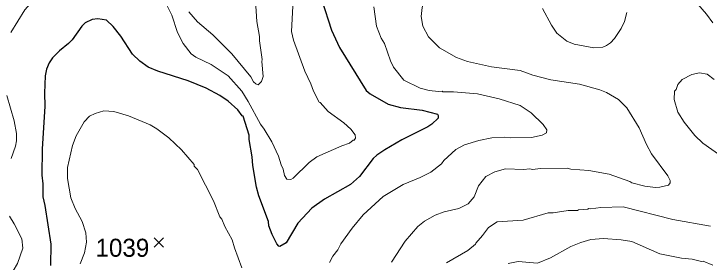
# Model space of a CAD drawing. Extents: x 265.7 to 292.1, y 7676.2 to 7704.2.
# Drawn here: x 287.156 to 290.234, y 7683.775 to 7684.876 of the extents above; entities that cross this region are included whole.
import ezdxf
from ezdxf.enums import TextEntityAlignment as Align

# ---------------------------------------------------------------- set-up
doc = ezdxf.new("R2010")
doc.units = 0
doc.header["$LTSCALE"] = 0.032
for name, color, linetype, lineweight in [('1', 7, 'Continuous', 25), ('2', 7, 'Continuous', 13), ('21', 7, 'Continuous', 25)]:
    doc.layers.add(name, color=color, linetype=linetype, lineweight=lineweight)
doc.layers.add('61', color=7, linetype='Continuous')

msp = doc.modelspace()

# ---------------------------------------------------------------- linework, layer by layer
at = {"layer": '1'}
for points in [[(288.519, 7684.9379), (288.5621, 7684.8038), (288.598, 7684.7272), (288.7161, 7684.5357), (288.7329, 7684.5214), (288.8127, 7684.4759), (288.8685, 7684.4607), (288.9643, 7684.4487), (289.0313, 7684.4312), (289.0353, 7684.4256), (289.0345, 7684.4128), (289.0066, 7684.3873), (288.9882, 7684.3753), (288.8733, 7684.3171), (288.7983, 7684.2732), (288.7632, 7684.2492), (288.7472, 7684.2341), (288.6866, 7684.1543), (288.6467, 7684.12), (288.5318, 7684.0545), (288.4751, 7684.0147), (288.4129, 7683.9484), (288.3618, 7683.8615), (288.3339, 7683.8447), (288.3283, 7683.8455), (288.3195, 7683.8559), (288.2988, 7683.8974), (288.2844, 7683.9357), (288.2828, 7683.9548), (288.2405, 7684.0697), (288.2302, 7684.108), (288.2142, 7684.2038), (288.211, 7684.2421), (288.1982, 7684.3187), (288.1982, 7684.3378), (288.1711, 7684.4216), (288.1671, 7684.4232), (288.1472, 7684.4511), (288.1049, 7684.4894), (288.0674, 7684.5142), (288.0067, 7684.5461), (287.9269, 7684.5796), (287.7929, 7684.6211), (287.7498, 7684.6395), (287.7131, 7684.6658)], [(287.5024, 7684.8509), (287.4721, 7684.8358), (287.4561, 7684.8206), (287.4138, 7684.7608), (287.3979, 7684.744), (287.3572, 7684.7121), (287.3269, 7684.6802), (287.3125, 7684.6586), (287.2997, 7684.6307), (287.2949, 7684.6012), (287.291, 7684.5246), (287.2934, 7684.4671), (287.2814, 7684.2756), (287.2798, 7684.1607), (287.2838, 7684.1224), (287.2838, 7684.0649), (287.2926, 7684.0266), (287.3197, 7683.8543), (287.3181, 7683.7601)], [(287.7131, 7684.6658), (287.6812, 7684.6977), (287.6293, 7684.7767), (287.595, 7684.8198), (287.5655, 7684.8477), (287.528, 7684.8533), (287.5024, 7684.8509)]]:
    msp.add_lwpolyline(points, dxfattribs=at)
at = {"layer": '2'}
for points in [[(287.5567, 7685.2331), (287.4936, 7685.2004), (287.4466, 7685.1621), (287.4107, 7685.123), (287.3325, 7685.0241), (287.2622, 7684.9602), (287.2048, 7684.8932), (287.1417, 7684.7927)], [(289.0106, 7685.1119), (289.0162, 7685.072), (289.0106, 7685.0233), (288.9794, 7684.9507), (288.9643, 7684.9044), (288.9587, 7684.8645), (288.9667, 7684.8214)], [(290.2505, 7684.8353), (290.2227, 7684.8741), (290.1357, 7684.9762)], [(287.9301, 7684.8852), (287.9692, 7684.8406), (288.0363, 7684.7831), (288.1208, 7684.6985), (288.2046, 7684.5964), (288.2174, 7684.574), (288.227, 7684.5653), (288.2381, 7684.5613), (288.2525, 7684.5756), (288.2597, 7684.598), (288.2541, 7684.665), (288.2557, 7684.673), (288.2429, 7684.756), (288.2437, 7684.7751), (288.231, 7684.8422), (288.2254, 7684.9331)], [(288.3906, 7684.9092), (288.3858, 7684.7975), (288.3937, 7684.7592), (288.4448, 7684.6219), (288.4704, 7684.5661), (288.4823, 7684.5325), (288.5071, 7684.4839), (288.5118, 7684.4831), (288.5469, 7684.4432), (288.6164, 7684.3929), (288.6483, 7684.3642), (288.6674, 7684.3402), (288.6682, 7684.3243), (288.6627, 7684.3163), (288.6587, 7684.3163), (288.6419, 7684.3027), (288.6084, 7684.2908), (288.4967, 7684.2413), (288.464, 7684.2173), (288.393, 7684.1471), (288.3818, 7684.1415), (288.3642, 7684.1431), (288.3538, 7684.1591), (288.3475, 7684.1878), (288.3387, 7684.207), (288.3275, 7684.2453), (288.298, 7684.3091), (288.2645, 7684.365), (288.2477, 7684.3873), (288.1935, 7684.4879), (288.1647, 7684.5325), (288.1041, 7684.6012), (288.0291, 7684.6514), (287.9621, 7684.6834), (287.9405, 7684.6985), (287.9054, 7684.7448), (287.8807, 7684.7927), (287.8551, 7684.8693), (287.8352, 7684.9108)], [(289.3553, 7684.3259), (289.4479, 7684.3275), (289.4957, 7684.3378), (289.5141, 7684.349), (289.5157, 7684.3618), (289.4989, 7684.3857), (289.4471, 7684.4368), (289.3984, 7684.4695), (289.3042, 7684.4998), (289.2085, 7684.5206), (289.1031, 7684.5301), (289.0553, 7684.5301), (289.0529, 7684.5333), (289.0361, 7684.5317), (288.9946, 7684.5365), (288.9547, 7684.5461), (288.8829, 7684.582), (288.8374, 7684.6395), (288.823, 7684.6682), (288.7967, 7684.7448), (288.7824, 7684.7687), (288.7608, 7684.8214), (288.7496, 7684.9076)], [(289.87, 7684.882), (289.8596, 7684.8422), (289.8452, 7684.8102), (289.8157, 7684.7663), (289.7982, 7684.748), (289.7798, 7684.7352), (289.7639, 7684.7288), (289.724, 7684.7248), (289.6362, 7684.7408), (289.6043, 7684.7552), (289.5604, 7684.7903), (289.5364, 7684.8254), (289.4973, 7684.8996)], [(288.9667, 7684.8214), (288.9914, 7684.7735), (289.0401, 7684.7256), (289.1159, 7684.6818), (289.1638, 7684.6642), (289.2707, 7684.6411), (289.3984, 7684.6243), (289.4542, 7684.6036), (289.534, 7684.5828), (289.6609, 7684.5637), (289.7511, 7684.5397), (289.7798, 7684.5269), (289.8325, 7684.4958), (289.87, 7684.4591), (289.925, 7684.3706), (289.957, 7684.2963), (289.9793, 7684.2549), (290.0511, 7684.1575), (290.0623, 7684.1368), (290.0615, 7684.1272), (290.0551, 7684.1168), (290.016, 7684.1072), (289.9969, 7684.1064), (289.949, 7684.112), (289.8915, 7684.1264), (289.8827, 7684.132), (289.7918, 7684.1655), (289.7016, 7684.1814), (289.6218, 7684.187), (289.6059, 7684.1918), (289.4862, 7684.191), (289.4542, 7684.1862), (289.4383, 7684.1886), (289.4143, 7684.1862), (289.333, 7684.1886), (289.2851, 7684.1758), (289.2452, 7684.1543), (289.2133, 7684.1128), (289.1941, 7684.0649), (289.167, 7684.0338), (289.1255, 7684.0131), (289.0616, 7683.9979), (289.0217, 7683.9835), (288.9739, 7683.9572), (288.9443, 7683.9325), (288.8885, 7683.8686), (288.8286, 7683.7753)], [(290.3009, 7684.2357), (290.2067, 7684.3027), (290.1708, 7684.337), (290.1245, 7684.3953), (290.0958, 7684.44), (290.0798, 7684.4958), (290.0814, 7684.5325), (290.0878, 7684.5405), (290.0958, 7684.5629), (290.115, 7684.5852), (290.158, 7684.6075), (290.1916, 7684.6139), (290.2251, 7684.6083), (290.257, 7684.5852)], [(287.125, 7684.5134), (287.1577, 7684.4017), (287.1681, 7684.3458), (287.1673, 7684.3123), (287.1633, 7684.29), (287.1441, 7684.2341)], [(287.4498, 7683.7681), (287.4681, 7683.816), (287.4777, 7683.8638), (287.4737, 7683.9053), (287.4577, 7683.9548), (287.4266, 7684.0123), (287.4075, 7684.0601), (287.3939, 7684.1463), (287.3931, 7684.1942), (287.4154, 7684.2916), (287.4314, 7684.3346), (287.4673, 7684.3969), (287.4913, 7684.4216), (287.5152, 7684.4344), (287.5535, 7684.4456), (287.5982, 7684.4432), (287.6636, 7684.424), (287.7594, 7684.3841), (287.7881, 7684.3666), (287.8416, 7684.3267), (287.8982, 7684.2724), (287.9541, 7684.2078), (287.9541, 7684.2014), (287.9692, 7684.1854), (288.0395, 7684.0474), (288.0674, 7683.9764), (288.077, 7683.9652), (288.0897, 7683.9325), (288.1224, 7683.8734), (288.132, 7683.8383), (288.1655, 7683.7505)], [(289.06, 7684.2253), (289.1135, 7684.274), (289.151, 7684.2947), (289.2149, 7684.3147), (289.2723, 7684.3259), (289.3298, 7684.3291), (289.3553, 7684.3259)], [(288.5541, 7683.7737), (288.5685, 7683.8016), (288.5908, 7683.8303), (288.6036, 7683.8567), (288.6539, 7683.9261), (288.7018, 7683.9851), (288.7911, 7684.0665), (288.8797, 7684.12), (288.9547, 7684.1503), (289.0018, 7684.1742), (289.0489, 7684.211), (289.06, 7684.2253)], [(289.072, 7683.7721), (289.1654, 7683.8271), (289.2005, 7683.8543), (289.2013, 7683.8599), (289.2316, 7683.8934), (289.2571, 7683.9285), (289.2962, 7683.9532), (289.4112, 7683.962), (289.5221, 7683.9939), (289.5436, 7683.9939), (289.6106, 7684.0035), (289.6513, 7684.0035), (289.6553, 7684.0067), (289.6976, 7684.0099), (289.7, 7684.0131), (289.7112, 7684.0115), (289.7543, 7684.0179), (289.8532, 7684.021), (290.0735, 7683.9636), (290.241, 7683.9349)], [(287.137, 7683.9788), (287.1577, 7683.9452), (287.1912, 7683.8782), (287.1952, 7683.8367), (287.1721, 7683.7697), (287.1529, 7683.7362)], [(290.2514, 7683.7617), (290.2075, 7683.7801), (290.2011, 7683.7785), (290.1596, 7683.7888), (290.1118, 7683.7928), (290.016, 7683.812), (289.8915, 7683.8662), (289.8452, 7683.8742), (289.767, 7683.8798), (289.7112, 7683.875), (289.6665, 7683.8622), (289.6218, 7683.8439), (289.5324, 7683.7944), (289.475, 7683.7705), (289.3888, 7683.7777), (289.3441, 7683.7697)]]:
    msp.add_lwpolyline(points, dxfattribs=at)
at = {"layer": '21'}
for p, q in [((287.7773, 7683.8828), (287.8185, 7683.8416)), ((287.8185, 7683.8828), (287.7773, 7683.8416))]:
    msp.add_line(p, q, dxfattribs=at)

# ---------------------------------------------------------------- texts
at = {"layer": '61'}
msp.add_text('1039', height=0.08, dxfattribs=at).set_placement((287.6364, 7683.799), align=Align.CENTER)

doc.saveas('drawing.dxf')
